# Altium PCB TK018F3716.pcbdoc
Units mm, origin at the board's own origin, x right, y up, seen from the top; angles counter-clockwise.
Board outline 35.7 x 43.6 mm, 2 copper layers (Top Layer, Bottom Layer), stack 1.58 mm thick; 14 components, 14 nets, 73 pads, 64 vias.
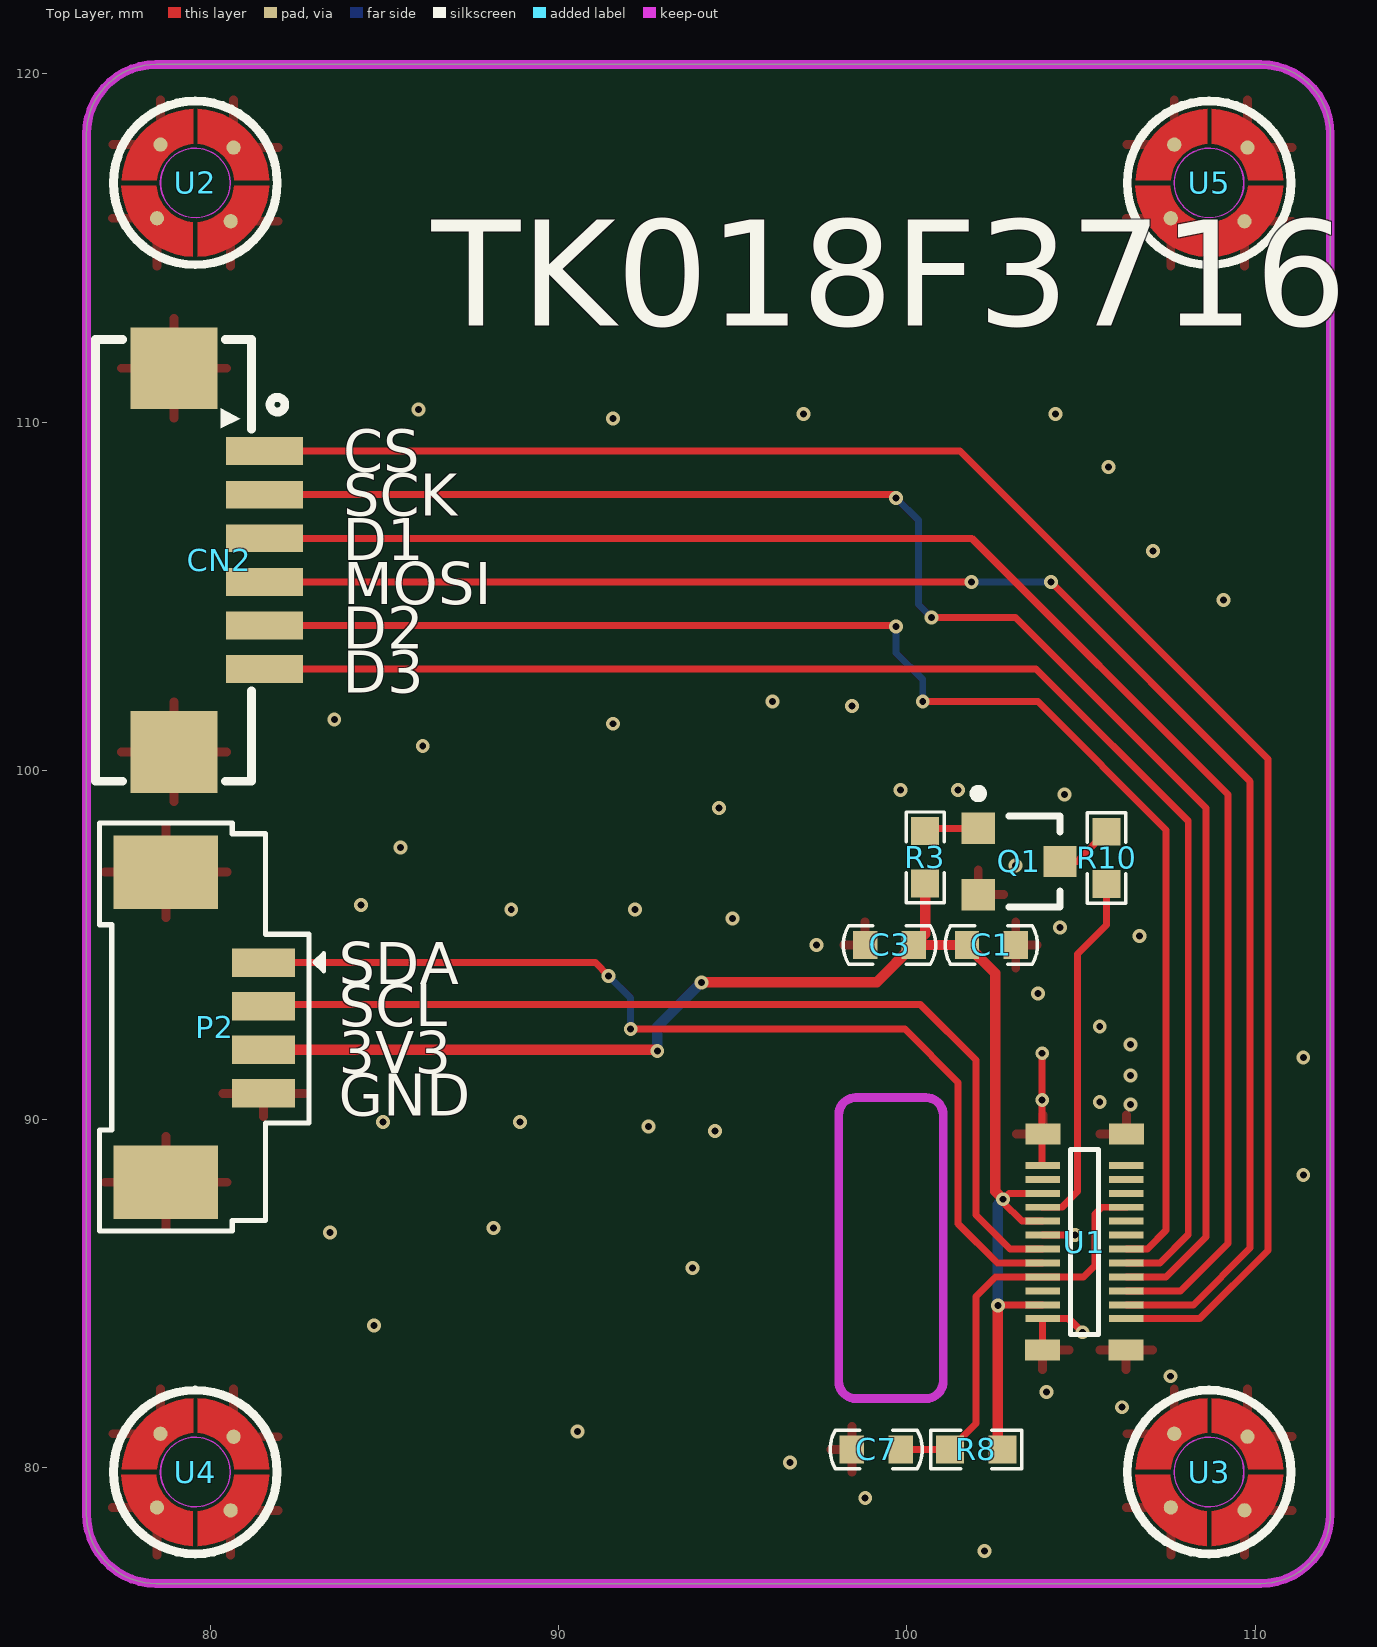
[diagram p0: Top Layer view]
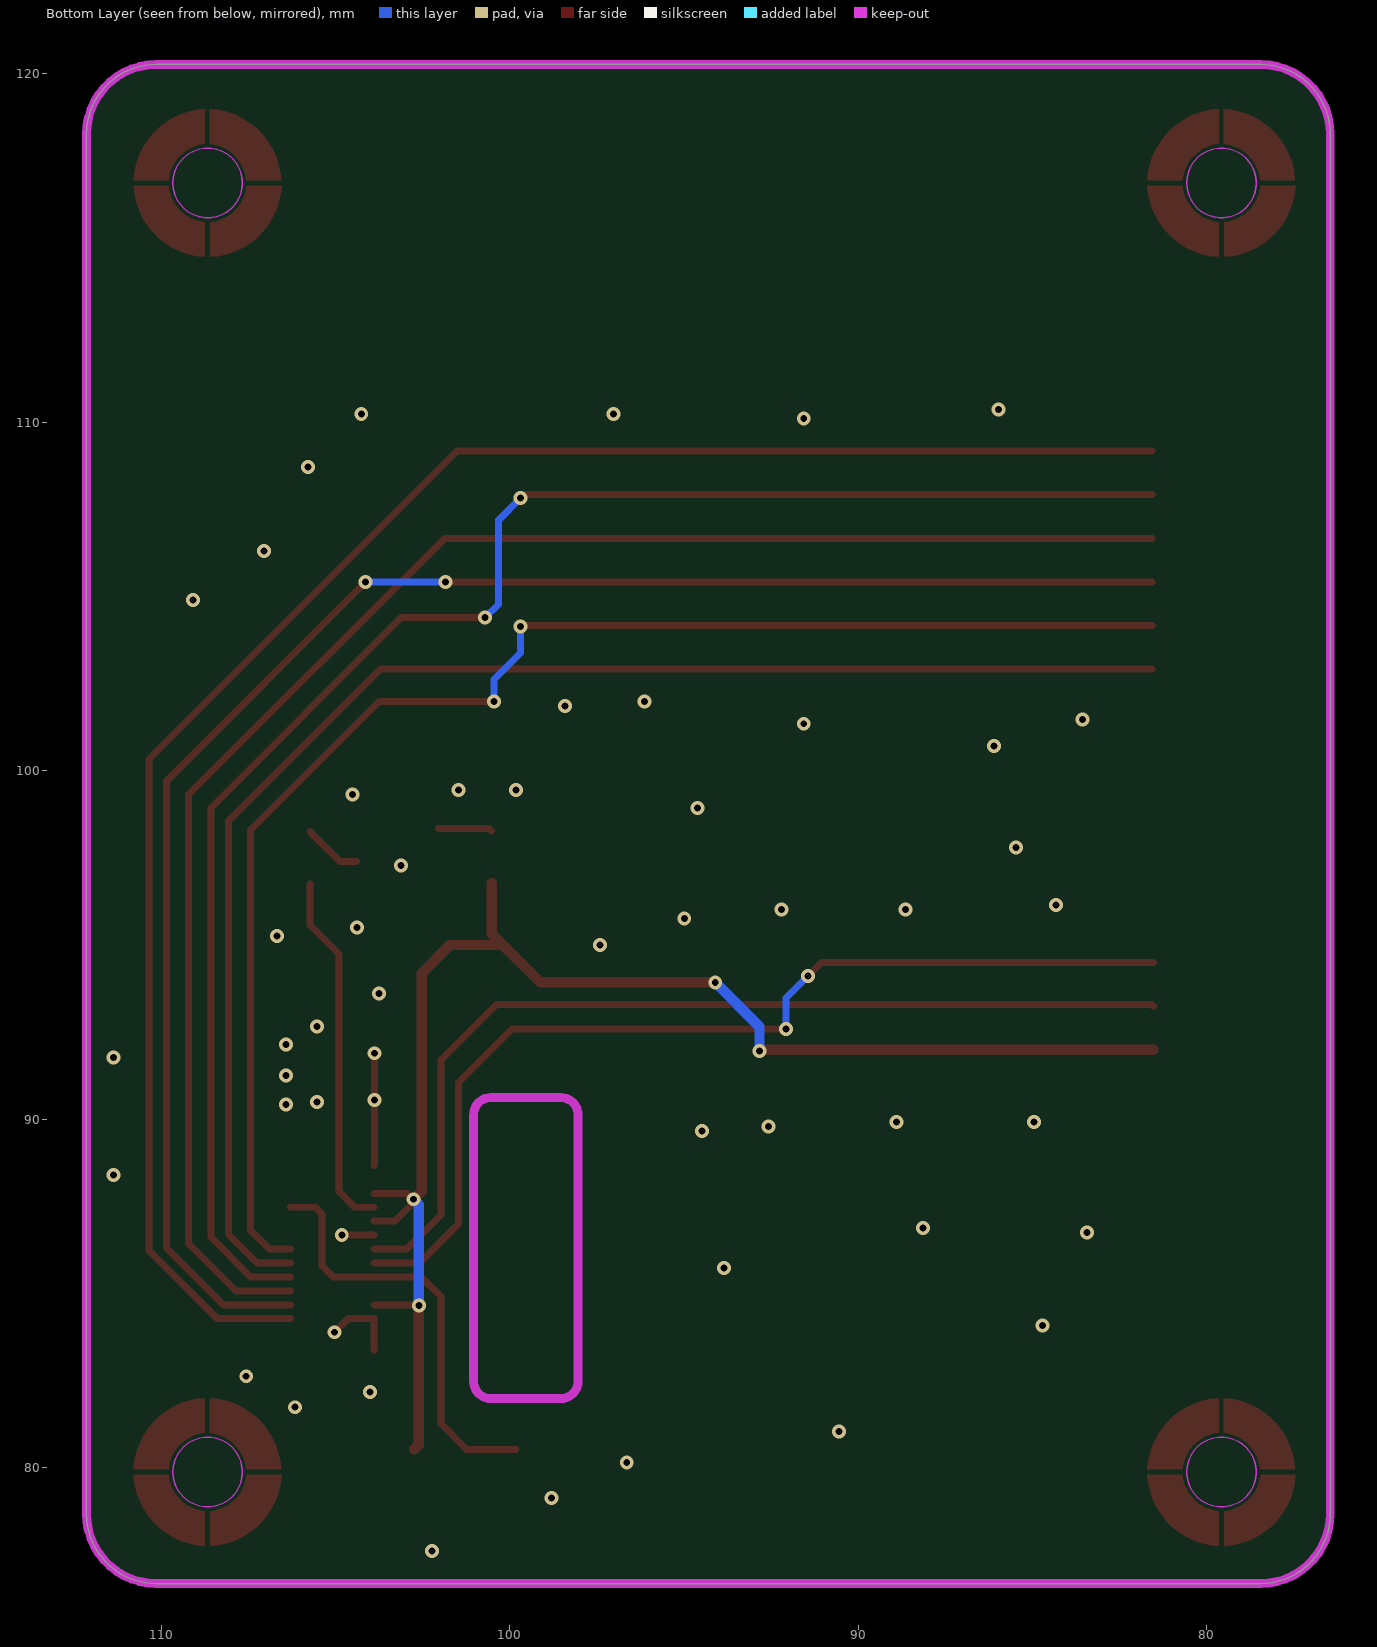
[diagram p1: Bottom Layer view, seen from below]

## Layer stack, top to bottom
Top Solder Mask Layer: solder mask 0.01, Dk 3.3
Top Layer: signal copper 0.035
Dielectric1: surface 1.51, FR4, Dk 4.5
Bottom Layer: signal copper 0.035
Bottom Solder Mask Layer: solder mask 0.01, Dk 3.3

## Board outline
78.454,120.269 110.154,120.269 cw(c110.154,118.269) 112.154,118.269 112.154,78.669 cw(c110.154,78.669) 110.154,76.669 78.454,76.669 cw(c78.454,78.669) 76.454,78.669 76.454,118.269 cw(c78.454,118.269)

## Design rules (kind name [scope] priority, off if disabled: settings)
BoardOutlineClearance copperThickness1oz [All] p0: genericclearance=0.254 ignorepadtopadclearanceinfootprint=FALSE except(0: Arc-SplitContinuation Track-SplitContinuation SMDPad-SplitContinuation THPad-SplitContinuation Via-SplitContinuation Fill-SplitContinuation Poly-SplitContinuation Region-SplitContinuation Text-SplitContinuation)
BoardOutlineClearance copperThickness2oz [All] p0: genericclearance=0.254 ignorepadtopadclearanceinfootprint=FALSE except(0: Arc-SplitContinuation Track-SplitContinuation SMDPad-SplitContinuation THPad-SplitContinuation Via-SplitContinuation Fill-SplitContinuation Poly-SplitContinuation Region-SplitContinuation Text-SplitContinuation)
BoardOutlineClearance otherClearance [All] p0: genericclearance=0.254 ignorepadtopadclearanceinfootprint=FALSE except(0: Arc-SplitContinuation Track-SplitContinuation SMDPad-SplitContinuation THPad-SplitContinuation Via-SplitContinuation Fill-SplitContinuation Poly-SplitContinuation Region-SplitContinuation Text-SplitContinuation)
Clearance copperThickness1oz [All] p1: gap=0.178 ignorepadtopadclearanceinfootprint=FALSE
Clearance copperThickness2oz [All] p1: gap=0.178 ignorepadtopadclearanceinfootprint=FALSE
Clearance otherClearance [All] p1: gap=0.178 ignorepadtopadclearanceinfootprint=FALSE
DiffPairsRouting differentialPair [All] p1: maxuncoupledlength=10 minlimit=6 maxlimit=Infinity mostfreqgap=6 toplayer_minwidth=5 toplayer_prefwidth=10 toplayer_maxwidth=100 bottomlayer_minwidth=5 bottomlayer_prefwidth=10 bottomlayer_maxwidth=100
PasteMaskExpansion pasteMaskExpansion [All] p1: expansion=0
PlaneConnect innerPlane [All] p1: planeconnectstyle=Relief reliefexpansion=0.508 reliefentries=4 reliefconductorwidth=0.254 reliefairgap=0.254
PolygonConnect copperRegion [All] p1: connectstyle=Relief reliefentries=4 reliefconductorwidth=10 polygonreliefangle="90 Angle" airgapwidth=10
RoutingVias viaSize [All] p1: viastyle="Through Hole" holewidth=7.874 minholewidth=7.874 maxholewidth=248.0314 width=7.874 minwidth=7.874 maxwidth=248.0314
SolderMaskExpansion solderMaskExpansion [All] p1: useseparateexpansions=TRUE expansion=2 expansionbottom=2
Width copperThickness1oz [All] p1: maxlimit=100 minlimit=5 preferedwidth=8
Width copperThickness2oz [All] p1: maxlimit=100 minlimit=8 preferedwidth=10

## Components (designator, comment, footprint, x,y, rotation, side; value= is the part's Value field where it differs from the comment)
C1 "" C0603-1 101.727,94.996 r0 top
C3 "" C0603-2 100.203,94.996 r180 top
C7 "" C0603-1 99.822,80.518 r180 top
CN2 "" CONN-SMD_6P-P1.25_HC-1.25-6PWT 80.264,106.045 r270 top
P2 "" BHEADSMD1x4 81.534,94.488 r90 top
Q1 "" SOT23A 102.051,98.343 r270 top
R3 "" R0603 100.527,96.763 r90 top
R8 "" R0603 102.743,80.518 r180 top
R10 "" R0603 105.734,98.247 r270 top
U1 "" TK014F1246-24P 106.299,84.269 r270 top
U2 "" SMTWEM2 79.627,116.969 r0 top
U3 "" SMTWEM2 108.727,79.969 r0 top
U4 "" SMTWEM2 79.627,79.969 r0 top
U5 "" SMTWEM2 108.727,116.969 r0 top

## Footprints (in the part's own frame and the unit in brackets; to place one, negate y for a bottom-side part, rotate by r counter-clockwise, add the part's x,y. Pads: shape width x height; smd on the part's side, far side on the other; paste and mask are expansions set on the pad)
BHEADSMD1x4 [mil]
  rect 32x71 smd: 1(0,0) 2(-49.21,0) 3(-98.43,0) 4(-147.64,0)
  rect 83x118 smd: 5(102.36,110.24) 6(-248.03,110.24)
  silkscreen extent -303,-68 158,185
C0603-1 [mm]
  rect 0.7x0.8 smd: 1(0,0) 2(1.4,0)
  silkscreen extent -0.62,-0.55 2.02,0.55
C0603-2 [mm]
  rect 0.7x0.8 smd: 1(0,0) 2(1.4,0)
  silkscreen extent -0.62,-0.55 2.02,0.55
CONN-SMD_6P-P1.25_HC-1.25-6PWT [mm]
  rect 0.8x2.2 smd: 1(-3.125,1.3) 2(-1.875,1.3) 3(-0.625,1.3) 4(0.625,1.3) 5(1.875,1.3) 6(3.125,1.3)
  rect 2.35x2.5 smd: 7(-5.505,-1.3) 8(5.505,-1.3)
  silkscreen extent -6.33,-3.56 6.35,1.88
R0603 [mm]
  rect 0.8x0.8 smd: 1(0,0) 2(1.5,0)
  silkscreen extent -0.55,-0.55 2.05,0.55
SMTWEM2 [mm]
  round 0.41 smd: 2(-1.15,-1.115) 2(-1.05,1) 2(0.965,-1.2) 2(1.05,0.915)
  Top Layer region: -2.159,-0.024 -1.856,0.98 -1.115,1.721 -0.111,2.024 -0.111,2.024 -0.111,1.022 -0.474,0.929 -0.788,0.724 -0.788,0.724 -1.043,0.385 -1.157,-0.024 -1.157,-0.024
  Top Layer region: 0.026,2.024 1.03,1.721 1.771,0.98 2.074,-0.024 2.074,-0.024 1.072,-0.024 0.979,0.339 0.774,0.654 0.774,0.654 0.435,0.908 0.026,1.022 0.026,1.022
  Top Layer region: -0.126,-2.224 -1.13,-1.921 -1.871,-1.18 -2.174,-0.176 -2.174,-0.176 -1.172,-0.176 -1.079,-0.539 -0.874,-0.854 -0.874,-0.854 -0.535,-1.108 -0.126,-1.222 -0.126,-1.222
  Top Layer region: 2.074,-0.176 1.771,-1.18 1.03,-1.921 0.026,-2.224 0.026,-2.224 0.026,-1.222 0.389,-1.129 0.704,-0.924 0.704,-0.924 0.958,-0.585 1.072,-0.176 1.072,-0.176
  Board Outline Layer circle w0.003: c-0.05,-0.1 r1
  Board Outline Layer region: 0.95,-0.1 0.851,-0.534 0.573,-0.882 0.173,-1.075 -0.273,-1.075 -0.673,-0.882 -0.951,-0.534 -1.05,-0.1 -1.05,-0.1 -0.951,0.334 -0.673,0.682 -0.273,0.875 0.173,0.875 0.573,0.682 0.851,0.334 0.95,-0.1
  Board Outline Layer region: 0.95,-0.1 0.851,-0.534 0.573,-0.882 0.173,-1.075 -0.273,-1.075 -0.673,-0.882 -0.951,-0.534 -1.05,-0.1 -1.05,-0.1 -0.951,0.334 -0.673,0.682 -0.273,0.875 0.173,0.875 0.573,0.682 0.851,0.334 0.95,-0.1
  silkscreen extent -2.4,-2.45 2.3,2.25
SOT23A [mm]
  rect 0.9x0.95 smd: 1(0,0) 2(1.9,0) 3(0.95,2.35)
  silkscreen extent -1.12,-0.12 2.25,2.35
TK014F1246-24P [mm]
  rect 0.2x1 smd: 1(0,0) 2(-0.4,0) 3(-0.8,0) 4(-1.2,0) 5(-1.6,0) 6(-2,0) 7(-2.4,0) 8(-2.8,0) 9(-3.2,0) 10(-3.6,0) 11(-4,0) 12(-4.4,0) 13(-4.4,-2.4) 14(-4,-2.4) 15(-3.6,-2.4) 16(-3.2,-2.4) 17(-2.8,-2.4) 18(-2.4,-2.4) 19(-2,-2.4) 20(-1.6,-2.4) 21(-1.2,-2.4) 22(-0.8,-2.4) 23(-0.4,-2.4) 24(0,-2.4)
  rect 0.6x1 smd: 25(-5.3,0.006) 25(-5.3,-2.394) 25(0.9,-0.006) 25(0.9,-2.406)
  silkscreen extent -4.85,-1.6 0.45,-0.8

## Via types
v1: diameter 0.4, hole 0.2, Top Layer to Bottom Layer, 64 vias

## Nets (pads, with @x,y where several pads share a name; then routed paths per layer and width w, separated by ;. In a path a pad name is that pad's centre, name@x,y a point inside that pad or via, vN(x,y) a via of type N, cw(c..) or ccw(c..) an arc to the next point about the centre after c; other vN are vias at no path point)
3.3V: C1.1 C3.1 P2.3 R3.1 R8.1 U1.15 U1.17 U1.23 | length 42.8
  Top Layer w0.2: v1(102.616,84.65) 102.635,84.669 U1.23 ; U1.17 103.304,87.069 102.766,87.607 v1(102.766,87.698) 102.937,87.869 U1.15
  Top Layer w0.3: P2.3 92.797,91.988 v1(92.837,91.948) ; v1(94.107,93.924) 99.131,93.924 C3.1 ; R3.1 100.527,95.32 C3.1 ; v1(102.616,84.65) 102.616,80.645 R8.1 ; v1(102.766,87.698) 102.537,87.927 102.537,94.186 C1.1 C3.1
  Bottom Layer w0.3: v1(92.837,91.948) 92.837,92.654 v1(94.107,93.924) ; v1(102.616,84.65) 102.616,87.548 v1(102.766,87.698)
$1N2: Q1.3 R10.1 | length 1.7
  Top Layer w0.2: Q1.3 104.88,97.393 R10.1
BL_CTR: Q1.1 R3.2 | length 1.6
  Top Layer w0.2: R3.2 100.607,98.343 Q1.1
CS: CN2.1 U1.1 | length 51.4
  Top Layer w0.2: CN2.1 101.523,109.17 110.363,100.33 110.363,86.233 108.399,84.269 U1.1
GND: C1.2 C3.2 C7.2 CN2.7 CN2.8 P2.4 P2.5 P2.6 Q1.2 U1.13 U1.18 U1.24 U1.25 U2.2 U3.2 U4.2 U5.2 | length 6.4
  Top Layer w0.2: v1(103.886,91.889) v1(103.886,90.551) 103.886,88.682 U1.13 ; U1.25@103.893,83.369 103.899,83.375 U1.24 104.648,84.269 v1(105.037,83.881) ; U1.18 104.796,86.669 v1@104.869,86.596
  other v1: 102.235,77.597 98.806,79.121 96.647,80.137 90.551,81.026 106.172,81.729 104.013,82.169 107.569,82.618 84.709,84.074 93.853,85.725 104.827,86.669 83.439,86.741 88.138,86.868 111.379,88.392 94.488,89.662 92.583,89.789 84.963,89.916 88.9,89.916 106.426,90.424 105.537,90.492 106.426,91.254 111.379,91.762 106.426,92.143 105.537,92.651 103.759,93.599 97.409,94.996 106.68,95.25 104.394,95.504 94.996,95.758 88.646,96.012 92.202,96.012 84.328,96.139 103.124,97.282 85.471,97.79 94.615,98.933 104.521,99.314 99.822,99.441 101.473,99.441 86.106,100.711 91.567,101.346 83.566,101.473 98.425,101.854 96.139,101.981 109.093,104.902 107.061,106.299 105.791,108.712 91.567,110.109 97.028,110.236 104.267,110.236 85.979,110.363
LED-: R10.2 U1.16 | length 10.4
  Top Layer w0.2: U1.16 104.455,87.469 104.902,87.916 104.902,94.742 105.734,95.574 R10.2
MOSI: CN2.4 U1.2 | length 48.3
  Top Layer w0.2: CN2.4 101.844,105.42 v1(101.854,105.41) ; v1(104.14,105.41) 109.855,99.695 109.855,86.301 108.223,84.669 U1.2
  Bottom Layer w0.2: v1(101.854,105.41) v1(104.14,105.41)
QSPI_D1: CN2.3 U1.3 | length 47.1
  Top Layer w0.2: CN2.3 101.864,106.67 109.22,99.314 109.22,86.428 107.861,85.069 U1.3
QSPI_D2: CN2.5 U1.6 | length 42
  Top Layer w0.2: CN2.5 99.665,104.17 v1(99.695,104.14) ; v1(100.457,101.981) 103.759,101.981 107.442,98.298 107.442,86.809 106.902,86.269 U1.6
  Bottom Layer w0.2: v1(99.695,104.14) 99.695,103.378 100.457,102.616 v1(100.457,101.981)
QSPI_D3: CN2.6 U1.5 | length 42.3
  Top Layer w0.2: CN2.6 103.709,102.92 108.077,98.552 108.077,86.682 107.264,85.869 U1.5
RST: C7.1 R8.2 U1.9 U1.21 | length 12.4
  Top Layer w0.2: C7.1 R8.2 101.981,81.256 101.981,84.904 102.546,85.469 U1.21 105.072,85.469 105.396,85.793 105.396,87.28 105.585,87.469 U1.9
SCK: CN2.2 U1.4 | length 47.2
  Top Layer w0.2: CN2.2 99.598,107.92 v1(99.695,107.823) ; v1(100.711,104.394) 103.124,104.394 108.585,98.933 108.585,86.612 107.442,85.469 U1.4
  Bottom Layer w0.2: v1(99.695,107.823) 100.33,107.188 100.33,104.775 v1(100.711,104.394)
SCL: P2.2 U1.19 | length 27.9
  Top Layer w0.2: P2.2 81.585,93.289 100.386,93.289 101.981,91.694 101.981,87.249 102.961,86.269 U1.19
SDA: P2.1 U1.20 | length 28.8
  Top Layer w0.2: P2.1 91.059,94.488 v1(91.44,94.107) ; v1(92.075,92.583) 99.944,92.583 101.473,91.054 101.473,86.995 102.599,85.869 U1.20
  Bottom Layer w0.2: v1(91.44,94.107) 92.075,93.472 v1(92.075,92.583)
pads on no net: U1.7 U1.8 U1.10 U1.11 U1.12 U1.14 U1.22

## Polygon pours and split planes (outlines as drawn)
GND on Top Layer (solid, remove dead copper, pour order 0): 76.2,120.396 112.522,120.396 112.522,76.2 76.2,76.2
GND on Bottom Layer (solid, remove dead copper, pour order 2): 76.2,120.396 112.522,120.396 112.522,76.2 76.2,76.2

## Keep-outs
Board Outline Layer:
  lines w0.254: 76.454,78.669 ccw(c78.454,78.669) 78.454,76.669 110.154,76.669 ccw(c110.154,78.669) 112.154,78.669 112.154,118.269 ccw(c110.154,118.269) 110.154,120.269 78.454,120.269 ccw(c78.454,118.269) 76.454,118.269 76.454,78.669 ; 98.044,82.476 ccw(c98.544,82.476) 98.544,81.976 100.544,81.976 ccw(c100.544,82.476) 101.044,82.476 101.044,90.119 ccw(c100.544,90.119) 100.544,90.619 98.544,90.619 ccw(c98.544,90.119) 98.044,90.119 98.044,82.476

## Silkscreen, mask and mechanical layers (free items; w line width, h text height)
Top Silkscreen Layer:
  text "TK018F3716" at 86.36,112.776 h3.05
  text "CS" at 83.82,108.585 h1.2
  text "SCK" at 83.82,107.315 h1.2
  text "D1" at 83.809,106.045 h1.2
  text "MOSI" at 83.82,104.775 h1.2
  text "D2" at 83.809,103.505 h1.2
  text "D3" at 83.809,102.235 h1.2
  text "SDA" at 83.693,93.869 h1.2
  text "SCL" at 83.693,92.669 h1.2
  text "3V3" at 83.689,91.313 h1.2
  text "GND" at 83.693,90.1 h1.2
